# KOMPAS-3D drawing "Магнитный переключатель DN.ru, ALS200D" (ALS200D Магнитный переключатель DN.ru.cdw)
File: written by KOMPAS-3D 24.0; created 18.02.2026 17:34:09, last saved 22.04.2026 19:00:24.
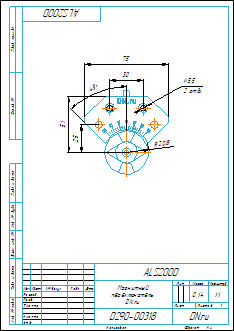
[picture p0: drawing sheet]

Document properties: Автор: R2D2; Форматы листов документа: A4; Полное имя файла: ALS200D Магнитный переключатель DN.ru.m3d; Масса: 0.14; Наименование: Магнитный переключатель DN.ru; Количество листов документа: 1; Примечание: D290-00318

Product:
- Part/product: Магнитный переключатель DN.ru  | designation ALS200D
    Масса: 0.14
    Раздел спецификации: Прочие изделия
    Примечание: D290-00318

Referenced files in E:\Работа\Зайцев\Для компаса\: чертеж DN.ru.cdt
Referenced files in E:\Работа\Зайцев\Аксессуары для пневмоприводов\Электропневматические позиционеры DN.ru\ALS200D Магнитный переключатель DN.ru\: ALS200D Магнитный переключатель DN.ru.m3d
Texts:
  чертеж DN.ru.cdt
  Магнитный
  переключатель
  ALS200D
  Магнитный переключатель DN.ru
  ALS200D Магнитный переключатель DN.ru
Dimensions and other numbers on the sheet: 1:1; 0; 1; 2; 0,14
